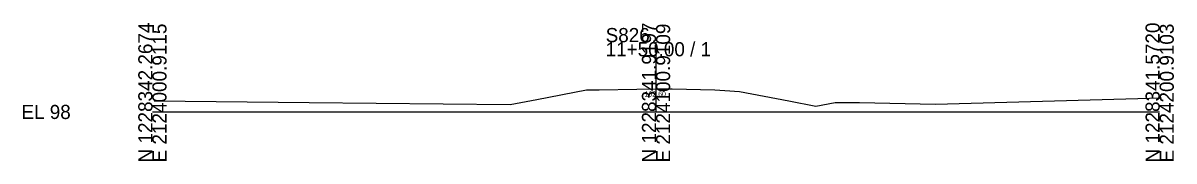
# Model space of a CAD drawing. Extents: x 2118382 to 2118616, y 1213030 to 1222057.
# Drawn here: x 2118381.9 to 2118610.4, y 1222030.1 to 1222057.4 of the extents above; entities that cross this region are included whole.
import ezdxf

# ---------------------------------------------------------------- set-up
doc = ezdxf.new("R2010")
doc.units = 0
for name, color, linetype in [('XS_CELL', 7, 'Continuous'), ('XS_X_GROUND', 7, 'Continuous'), ('XS_X_GROUND_TX', 7, 'Continuous')]:
    doc.layers.add(name, color=color, linetype=linetype)

msp = doc.modelspace()

# ---------------------------------------------------------------- linework, layer by layer
at = {"layer": 'XS_CELL'}
for p, q in [((2118507.6, 1222039.8), (2118507.6, 1222053.61)), ((2118407.6, 1222039.8), (2118507.6, 1222039.8)), ((2118507.6, 1222039.8), (2118607.6, 1222039.8))]:
    msp.add_line(p, q, dxfattribs=at)
at = {"layer": 'XS_X_GROUND'}
for p, q in [((2118483.91, 1222042.29), (2118493.8, 1222044.16)), ((2118493.8, 1222044.16), (2118494.64, 1222044.16)), ((2118494.64, 1222044.16), (2118496.33, 1222044.17)), ((2118496.33, 1222044.17), (2118503.76, 1222044.32)), ((2118503.76, 1222044.32), (2118507.6, 1222044.4)), ((2118507.6, 1222044.4), (2118507.95, 1222044.4)), ((2118507.95, 1222044.4), (2118510.78, 1222044.35)), ((2118510.78, 1222044.35), (2118519.27, 1222044.17)), ((2118519.27, 1222044.17), (2118521.26, 1222044.05)), ((2118521.26, 1222044.05), (2118524.15, 1222043.83)), ((2118524.15, 1222043.83), (2118534, 1222041.97)), ((2118407.95, 1222041.99), (2118438.75, 1222041.67)), ((2118438.75, 1222041.67), (2118478.67, 1222041.29)), ((2118478.67, 1222041.29), (2118483.91, 1222042.29)), ((2118534, 1222041.97), (2118539.3, 1222040.97)), ((2118539.3, 1222040.97), (2118543.19, 1222041.68)), ((2118543.19, 1222041.68), (2118547.99, 1222041.68)), ((2118547.99, 1222041.68), (2118563.09, 1222041.37)), ((2118563.09, 1222041.37), (2118607.95, 1222042.58))]:
    msp.add_line(p, q, dxfattribs=at)

# ---------------------------------------------------------------- texts
at = {"layer": 'XS_CELL'}
for s, p in [('N 1228342.2674', (2118407.6, 1222029.8)), ('E 2124000.9115', (2118410.4, 1222029.8)), ('N 1228341.9197', (2118507.6, 1222029.8)), ('E 2124100.9109', (2118510.4, 1222029.8)), ('N 1228341.5720', (2118607.6, 1222029.8)), ('E 2124200.9103', (2118610.4, 1222029.8))]:
    msp.add_text(s, height=2.8, rotation=90, dxfattribs=at).set_placement(p)
for s, p in [('S826', (2118497.6, 1222053.61)), ('11+50.00 / 1', (2118497.6, 1222050.81)), ('EL 98', (2118381.6, 1222038.4))]:
    msp.add_text(s, height=2.8, dxfattribs=at).set_placement(p)
at = {"layer": 'XS_X_GROUND_TX'}
msp.add_text('102.60', height=1, dxfattribs=at).set_placement((2118505.33, 1222042.85))

doc.saveas('drawing.dxf')
